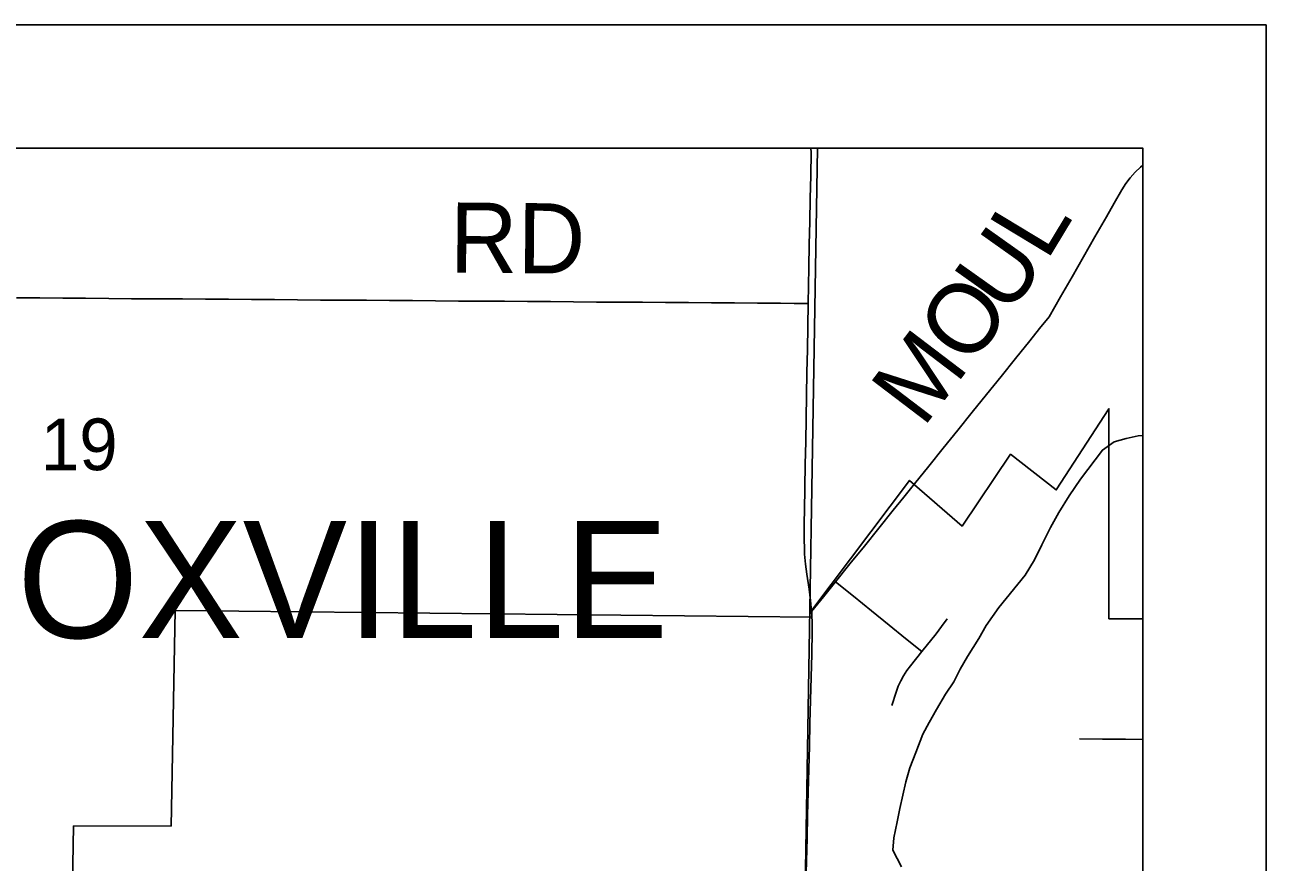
# Model space of a CAD drawing. Extents: x -11.1 to 34, y -3.9 to 22.
# Drawn here: x 7.994 to 9, y 20.321 to 21 of the extents above; entities that cross this region are included whole.
import ezdxf

# ---------------------------------------------------------------- set-up
doc = ezdxf.new("R2010")
doc.units = 0
for name, color, linetype in [('GM_X_City_Street', 7, 'Continuous'), ('GM_X_Corporation', 7, 'Continuous'), ('GM_X_Corporation_Text', 7, 'Continuous'), ('GM_X_County_Road', 7, 'Continuous'), ('GM_X_County_Road_Text', 7, 'Continuous'), ('GM_X_Minor_River', 7, 'Continuous'), ('GM_X_Section_Text', 7, 'Continuous'), ('GM_X_State_Route', 7, 'Continuous'), ('GM_X_Township_Road', 7, 'Continuous'), ('GM_X_Township_Road_Text', 7, 'Continuous'), ('SH_Data', 7, 'Continuous')]:
    doc.layers.add(name, color=color, linetype=linetype)

msp = doc.modelspace()

# ---------------------------------------------------------------- linework, layer by layer
at = {"layer": 'GM_X_City_Street'}
for points in [[(8.6509, 20.5485), (8.6654, 20.5368), (8.68, 20.5251), (8.6945, 20.5134), (8.7077, 20.5027), (8.721, 20.492)], [(8.6966, 20.4482), (8.7002, 20.4592), (8.7018, 20.4638), (8.7038, 20.4682), (8.7061, 20.4724), (8.7087, 20.4765), (8.7116, 20.4804), (8.721, 20.492), (8.7326, 20.5064), (8.7348, 20.5093), (8.7369, 20.5122), (8.7413, 20.5186)], [(8.8488, 20.4212), (8.8674, 20.4211), (8.886, 20.4209), (8.9, 20.4208)]]:
    msp.add_lwpolyline(points, dxfattribs=at)
at = {"layer": 'GM_X_Corporation'}
for points in [[(8.9, 19.2515), (8.9, 20.9), (2.1, 20.9)], [(8.9, 19.2515), (8.9, 20.9), (7.452, 20.9), (7.4494, 20.7828), (7.436, 20.2539), (7.4229, 19.6584), (7.4185, 19.2665)], [(8.9, 19.7521), (8.9, 20.5184), (8.8726, 20.5186), (8.8726, 20.6888), (8.8298, 20.623), (8.7928, 20.6519), (8.7535, 20.5937), (8.711, 20.6307), (8.6317, 20.5256), (8.6317, 20.5199), (8.1158, 20.5253), (8.1124, 20.3505), (8.0334, 20.3506), (8.0318, 20.2716)]]:
    msp.add_lwpolyline(points, dxfattribs=at)
for points in [[(8.6363, 20.9), (7.4509, 20.9), (7.4373, 20.2744), (8.6259, 20.2667)], [(8.9, 20.2647), (8.9, 20.9), (8.6363, 20.9), (8.6259, 20.2667)]]:
    msp.add_lwpolyline(points, close=True, dxfattribs=at)
at = {"layer": 'GM_X_County_Road'}
for points in [[(8.7149, 20.6278), (8.7266, 20.6423), (8.7383, 20.6569), (8.75, 20.6714), (8.7617, 20.6859), (8.7734, 20.7004), (8.7851, 20.7149), (8.7968, 20.7294), (8.8085, 20.7439), (8.8163, 20.7537), (8.8242, 20.7634), (8.8334, 20.7795), (8.8427, 20.7957), (8.852, 20.8119), (8.8612, 20.8281), (8.8705, 20.8442), (8.8768, 20.8553), (8.8831, 20.8663), (8.8863, 20.8713), (8.8898, 20.876), (8.8937, 20.8805), (8.898, 20.8846), (8.9, 20.8862)], [(8.6315, 20.5244), (8.6412, 20.5364), (8.6509, 20.5485), (8.6626, 20.563), (8.6743, 20.5775), (8.686, 20.592), (8.6977, 20.6065), (8.7063, 20.6172), (8.7149, 20.6278)]]:
    msp.add_lwpolyline(points, dxfattribs=at)
at = {"layer": 'GM_X_Minor_River'}
for points in [[(8.9, 20.6672), (8.8963, 20.6669), (8.8864, 20.6648), (8.8768, 20.662), (8.8672, 20.6553), (8.8496, 20.6318), (8.8402, 20.6183), (8.832, 20.6048), (8.8252, 20.5925), (8.8181, 20.5786), (8.8122, 20.5662), (8.8047, 20.5538)], [(8.8047, 20.5538), (8.7833, 20.5277), (8.773, 20.5132), (8.7671, 20.5027), (8.7579, 20.4881), (8.752, 20.4776), (8.7468, 20.4675), (8.7401, 20.4574), (8.7329, 20.4451), (8.7269, 20.4346), (8.7217, 20.4249), (8.716, 20.4102), (8.7112, 20.3978), (8.7078, 20.3865), (8.7056, 20.3756), (8.7031, 20.3647), (8.7009, 20.3541), (8.6983, 20.3409), (8.6973, 20.331), (8.7045, 20.3176)]]:
    msp.add_lwpolyline(points, dxfattribs=at)
at = {"layer": 'GM_X_State_Route'}
msp.add_line((8.6274, 20.3221), (8.6269, 20.3035), dxfattribs=at)
for points in [[(8.631, 20.9), (8.6312, 20.8964), (8.6308, 20.8778), (8.6304, 20.8592), (8.6301, 20.8405), (8.6297, 20.8219), (8.6293, 20.8033), (8.6291, 20.7887), (8.6288, 20.7741), (8.6284, 20.7555), (8.6281, 20.7368), (8.6278, 20.7182), (8.6274, 20.6995), (8.6271, 20.6809), (8.6268, 20.6623), (8.6264, 20.6436), (8.6261, 20.625), (8.6258, 20.6063), (8.6256, 20.5969), (8.6254, 20.5875), (8.6258, 20.571), (8.6265, 20.5628), (8.6276, 20.5546), (8.6295, 20.5425), (8.6307, 20.5334), (8.6315, 20.5244)], [(8.6315, 20.5244), (8.6319, 20.5164), (8.632, 20.5144)], [(8.632, 20.5144), (8.6321, 20.5084), (8.6316, 20.4898), (8.6312, 20.4712), (8.6307, 20.4525), (8.6302, 20.4339), (8.6298, 20.4153), (8.6293, 20.3966), (8.6288, 20.378), (8.6283, 20.3594), (8.6279, 20.3407), (8.6274, 20.3221)]]:
    msp.add_lwpolyline(points, dxfattribs=at)
at = {"layer": 'GM_X_Township_Road'}
msp.add_lwpolyline([(7.9872, 20.7787), (8.0059, 20.7786), (8.0245, 20.7784), (8.0431, 20.7783), (8.0618, 20.7782), (8.0804, 20.778), (8.0991, 20.7779), (8.1104, 20.7778), (8.1216, 20.7778), (8.1403, 20.7776), (8.1589, 20.7775), (8.1776, 20.7774), (8.1962, 20.7772), (8.2149, 20.7771), (8.2335, 20.7769), (8.2521, 20.7768), (8.2708, 20.7767), (8.2894, 20.7765), (8.3081, 20.7764), (8.3267, 20.7763), (8.3453, 20.7761), (8.364, 20.776), (8.3826, 20.7759), (8.4013, 20.7757), (8.4199, 20.7756), (8.4385, 20.7755), (8.4572, 20.7753), (8.4758, 20.7752), (8.4945, 20.7751), (8.5131, 20.7749), (8.5317, 20.7748), (8.5504, 20.7747), (8.569, 20.7745), (8.5877, 20.7744), (8.6063, 20.7743), (8.6175, 20.7742), (8.6288, 20.7741)], dxfattribs=at)
at = {"layer": 'SH_Data'}
for p, q in [((2, 21), (9, 21)), ((9, 21), (9, 14)), ((2.1, 20.9), (8.9, 20.9)), ((8.9, 20.9), (8.9, 14.1))]:
    msp.add_line(p, q, dxfattribs=at)

# ---------------------------------------------------------------- texts
at = {"layer": 'GM_X_Corporation_Text'}
msp.add_text('NEW KNOXVILLE', height=0.094697, rotation=0, dxfattribs=at).set_placement((7.481, 20.503))
at = {"layer": 'GM_X_County_Road_Text'}
for s, rotation, p in [('L', 58.8536, (8.8221, 20.8077)), ('U', 54.6215, (8.7907, 20.7631)), ('O', 52.7999, (8.7593, 20.7216)), ('M', 52.75, (8.7219, 20.6725))]:
    msp.add_text(s, height=0.0568, rotation=rotation, dxfattribs=at).set_placement(p)
at = {"layer": 'GM_X_Section_Text'}
msp.add_text('19', height=0.04186, rotation=0, dxfattribs=at).set_placement((8.0068, 20.639))
at = {"layer": 'GM_X_Township_Road_Text'}
msp.add_text('RD', height=0.05682, rotation=359.5056, dxfattribs=at).set_placement((8.3381, 20.7992))

doc.saveas('drawing.dxf')
